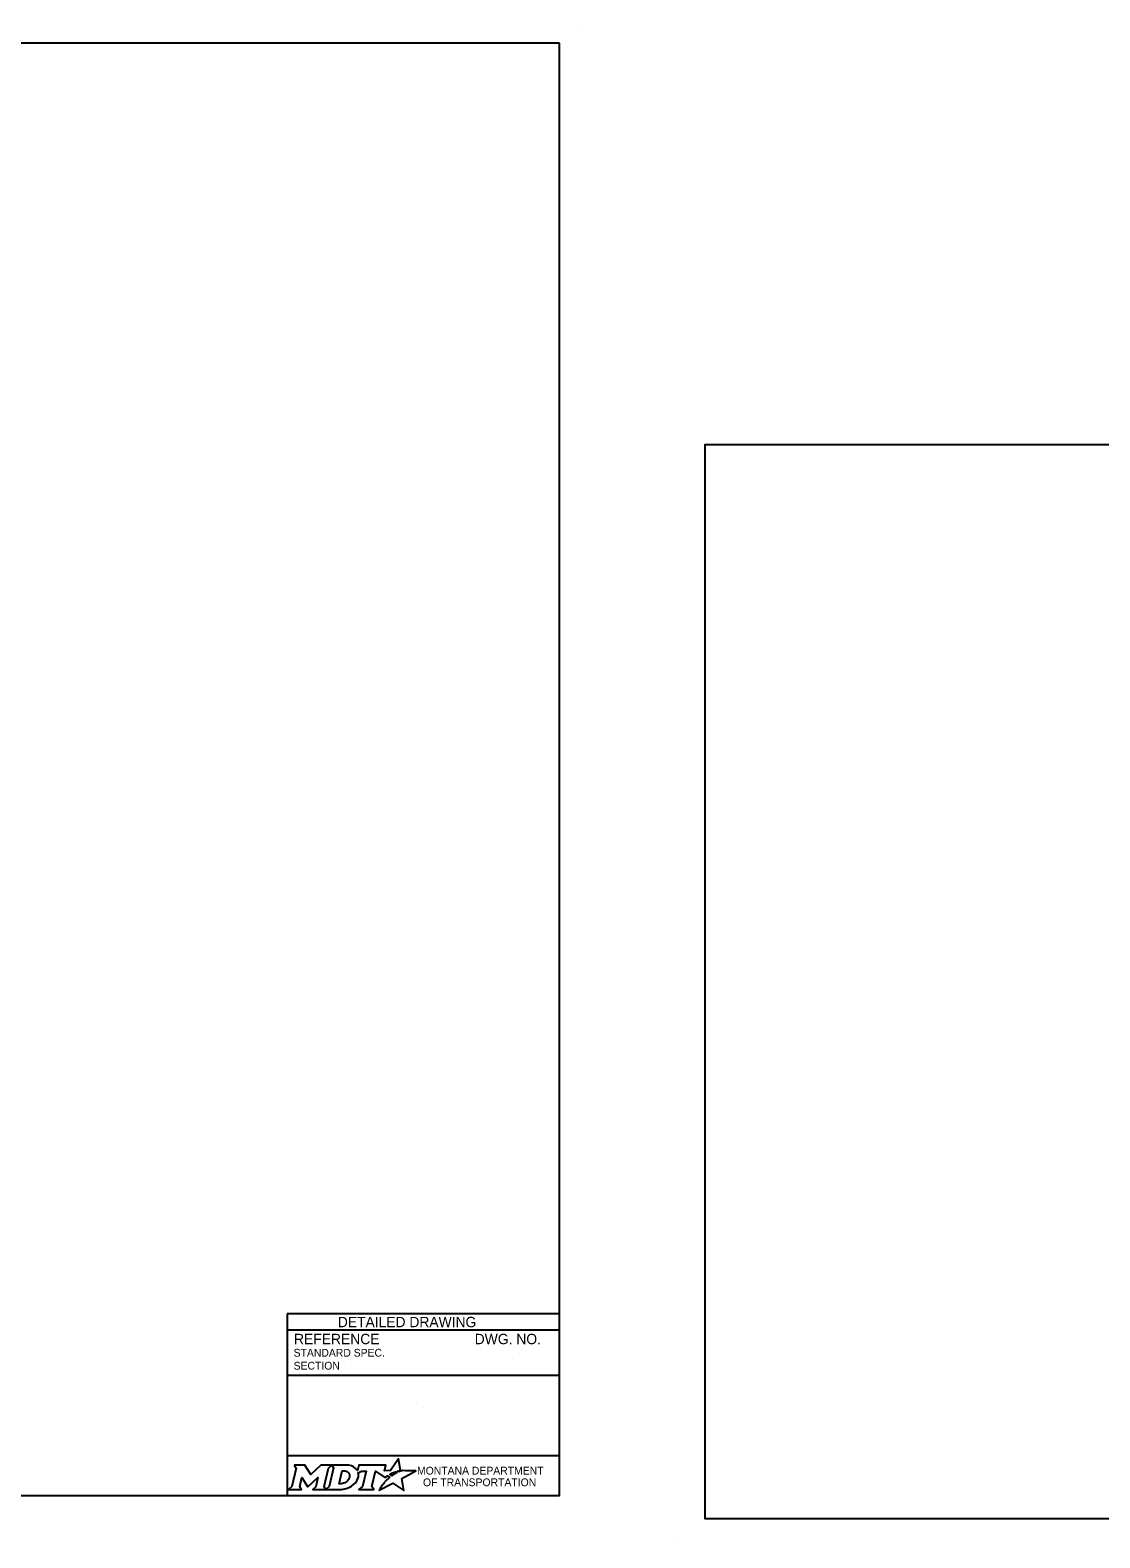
# Model space of a CAD drawing. Extents: x 49991.4 to 50021, y 49987.6 to 50011.4.
# Drawn here: x 50004.53 to 50012.79, y 49999.74 to 50011.36 of the extents above; entities that cross this region are included whole.
import ezdxf

# ---------------------------------------------------------------- set-up
doc = ezdxf.new("R2010")
doc.units = 0
doc.layers.add('Level 1', color=7, linetype='Continuous')
doc.layers.add('Level 2', color=7, linetype='Continuous')

msp = doc.modelspace()

# ---------------------------------------------------------------- linework, layer by layer
at = {"layer": 'Level 1'}
for p, q in [((50008.765, 50011.363), (50008.765, 50011.363)), ((50009.537, 49999.736), (50009.537, 49999.736))]:
    msp.add_line(p, q, dxfattribs=at)
for points in [[(50008.615, 50011.263), (50000.336, 50011.263), (50000.336, 50000.062), (50008.615, 50000.062)], [(50020.938, 50008.165), (50009.737, 50008.165), (50009.737, 49999.886), (50020.938, 49999.886)]]:
    msp.add_lwpolyline(points, close=True, dxfattribs=at)
at = {"layer": 'Level 2'}
for p, q in [((50008.615, 50001.462), (50006.515, 50001.462)), ((50006.515, 50001.462), (50006.515, 50000.062)), ((50008.615, 50001.337), (50006.515, 50001.337)), ((50007.009, 50001.063), (50007.009, 50001.063)), ((50008.251, 50001.122), (50008.251, 50001.122)), ((50008.615, 50000.987), (50006.515, 50000.987)), ((50007.565, 50000.738), (50007.565, 50000.738)), ((50008.615, 50000.369), (50006.515, 50000.369))]:
    msp.add_line(p, q, dxfattribs=at)
for points in [[(50007.377, 50000.245), (50007.367, 50000.25), (50007.378, 50000.253), (50007.39, 50000.255), (50007.373, 50000.345), (50007.313, 50000.254), (50007.266, 50000.253), (50007.276, 50000.297), (50007.067, 50000.297), (50007.057, 50000.255), (50007.051, 50000.263)], [(50006.57, 50000.297), (50006.584, 50000.274), (50006.551, 50000.131), (50006.525, 50000.108), (50006.627, 50000.108), (50006.613, 50000.131), (50006.629, 50000.201), (50006.673, 50000.132), (50006.678, 50000.132), (50006.753, 50000.202), (50006.737, 50000.13), (50006.712, 50000.108), (50006.814, 50000.108), (50006.8, 50000.132), (50006.833, 50000.274)], [(50006.833, 50000.274), (50006.859, 50000.297), (50006.776, 50000.297), (50006.697, 50000.224), (50006.652, 50000.297), (50006.57, 50000.297)], [(50006.972, 50000.297), (50006.859, 50000.297), (50006.873, 50000.275), (50006.839, 50000.131), (50006.814, 50000.108), (50006.925, 50000.108)], [(50006.996, 50000.211), (50006.995, 50000.203), (50006.992, 50000.193), (50006.988, 50000.185), (50006.982, 50000.178), (50006.976, 50000.171), (50006.968, 50000.164), (50006.959, 50000.16), (50006.95, 50000.156), (50006.941, 50000.154), (50006.932, 50000.153), (50006.916, 50000.153), (50006.94, 50000.253), (50006.956, 50000.253), (50006.963, 50000.252), (50006.971, 50000.25), (50006.977, 50000.247), (50006.983, 50000.243), (50006.988, 50000.238), (50006.992, 50000.232), (50006.995, 50000.226), (50006.996, 50000.218), (50006.996, 50000.215), (50006.996, 50000.211)], [(50007.064, 50000.238), (50007.088, 50000.251), (50007.125, 50000.251), (50007.097, 50000.131), (50007.069, 50000.108), (50007.185, 50000.108), (50007.168, 50000.131), (50007.196, 50000.251), (50007.268, 50000.2), (50007.289, 50000.215), (50007.309, 50000.204)], [(50007.253, 50000.148), (50007.237, 50000.124), (50007.233, 50000.116), (50007.227, 50000.107), (50007.225, 50000.103), (50007.33, 50000.156), (50007.414, 50000.101), (50007.401, 50000.194), (50007.508, 50000.252), (50007.458, 50000.253), (50007.428, 50000.253), (50007.407, 50000.254), (50007.401, 50000.252), (50007.396, 50000.251), (50007.387, 50000.249), (50007.377, 50000.245)], [(50007.327, 50000.217), (50007.324, 50000.215), (50007.306, 50000.225), (50007.316, 50000.231), (50007.32, 50000.233), (50007.329, 50000.237), (50007.335, 50000.239), (50007.343, 50000.243), (50007.35, 50000.245), (50007.362, 50000.238), (50007.358, 50000.236), (50007.353, 50000.233), (50007.349, 50000.231), (50007.344, 50000.228), (50007.342, 50000.227), (50007.339, 50000.225), (50007.337, 50000.224), (50007.334, 50000.222), (50007.332, 50000.221), (50007.329, 50000.219), (50007.327, 50000.217)], [(50006.97, 50000.116), (50006.979, 50000.118), (50006.992, 50000.124), (50007.012, 50000.135)], [(50007.267, 50000.164), (50007.267, 50000.164)]]:
    msp.add_lwpolyline(points, dxfattribs=at)
for centre, radius, start, end in [((50006.995, 50000.219), 0.0709, 339.5329, 15.8582), ((50006.951, 50000.236), 0.118, 300.9103, 339.1383)]:
    msp.add_arc(centre, radius, start, end, dxfattribs=at)
for centre, major_axis, ratio, start_param, end_param in [((50006.97, 50000.25), (0.0834, -0.0037), 0.568097, 0.61298, 1.570796), ((50007.026, 50000.257), (0.0361, -0.0295), 0.469099, 1.225588, 1.570796), ((50006.925, 50000.257), (0, 0.148), 0.987302, 3.139398, 3.456847), ((50007.26, 50000.156), (-0.00694, -0.00806), 0.008222, 0, 3.137361), ((50007.276, 50000.174), (-0.0098, -0.0102), 0.016458, 3.141593, 6.279097), ((50007.297, 50000.194), (-0.0112, -0.0097), 0.021651, 3.157348, 6.283185)]:
    msp.add_ellipse(centre, major_axis=major_axis, ratio=ratio, start_param=start_param, end_param=end_param, dxfattribs=at)

# ---------------------------------------------------------------- texts
for s, height, p in [('DETAILED DRAWING', 0.0799, (50006.906, 50001.36)), ('REFERENCE', 0.08, (50006.568, 50001.229)), ('DWG. NO.', 0.08, (50007.962, 50001.229)), ('STANDARD SPEC.', 0.06, (50006.565, 50001.133)), ('SECTION', 0.06, (50006.565, 50001.033))]:
    msp.add_text(s, height=height, dxfattribs=at).set_placement(p)
for s, p in [('MONTANA DEPARTMENT', (50007.517, 50000.224)), ('OF TRANSPORTATION', (50007.563, 50000.134))]:
    msp.add_text(s, height=0.06, rotation=360, dxfattribs=at).set_placement(p)

doc.saveas('drawing.dxf')
